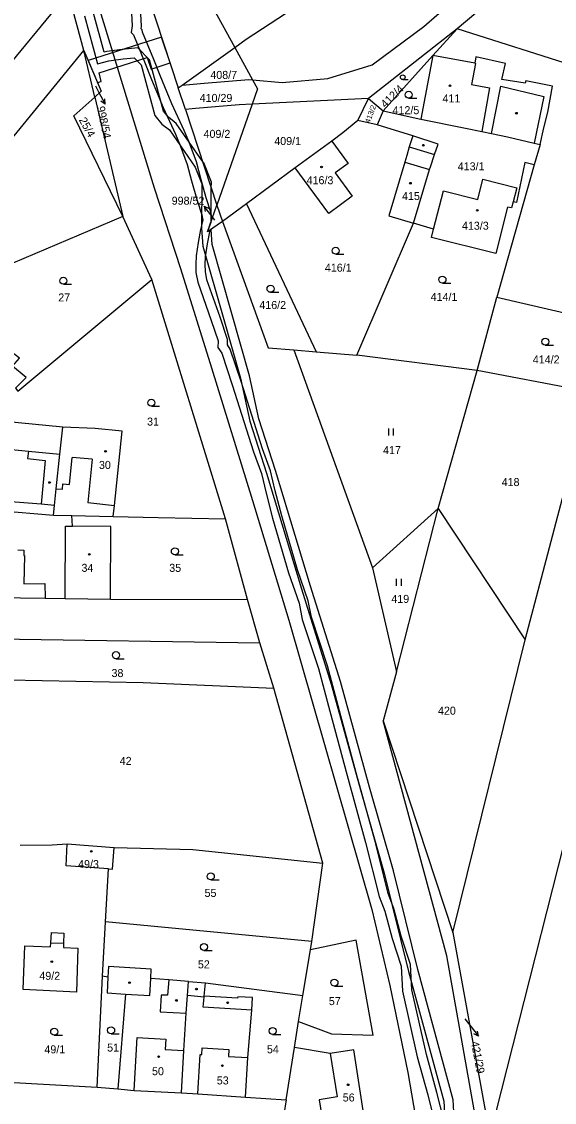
# Model space of a CAD drawing. Extents: x -757266 to -753360, y -1162585 to -1157740.
# Drawn here: x -754656.1 to -754542.9, y -1161271.1 to -1161041.7 of the extents above; entities that cross this region are included whole.
import ezdxf

# ---------------------------------------------------------------- set-up
doc = ezdxf.new("R2010")
doc.units = 0
for name, color, linetype in [('Hranice parcel', 7, 'Continuous'), ('Parcelní čísla', 7, 'Continuous'), ('Pop  PČ popisy', 7, 'Continuous'), ('Poz předměty', 7, 'Continuous'), ('Vnitřní kresba', 7, 'Continuous'), ('Věcná břemena k části', 7, 'Continuous'), ('Značky budov', 7, 'Continuous'), ('Značky kultur', 7, 'Continuous')]:
    doc.layers.add(name, color=color, linetype=linetype)

msp = doc.modelspace()

# ---------------------------------------------------------------- linework, layer by layer
at = {"layer": 'Hranice parcel'}
for p, q in [((-754505.44, -1160994.03), (-754563.51, -1161043.2)), ((-754632.76, -1161025.61), (-754622.81, -1161055.74)), ((-754646.22, -1161035.54), (-754676.57, -1161072.39)), ((-754642.86, -1161047.81), (-754646.22, -1161035.54)), ((-754616.16, -1161037.43), (-754610.8, -1161047.18)), ((-754563.51, -1161043.2), (-754582.39, -1161057.99)), ((-754563.51, -1161043.2), (-754568.69, -1161048.85)), ((-754518.76, -1161057.4), (-754563.51, -1161043.2)), ((-754640.55, -1161057.68), (-754642.86, -1161047.81)), ((-754622, -1161055.16), (-754610.8, -1161047.18)), ((-754610.8, -1161047.18), (-754607.04, -1161054.04)), ((-754579.29, -1161060.63), (-754568.69, -1161048.85)), ((-754568.69, -1161048.85), (-754571.3, -1161062.39)), ((-754622.81, -1161055.74), (-754622, -1161055.16)), ((-754621.3, -1161060.33), (-754622.81, -1161055.74)), ((-754640.55, -1161057.68), (-754634.62, -1161083.05)), ((-754582.39, -1161057.99), (-754607.11, -1161059.19)), ((-754584.62, -1161062.68), (-754582.39, -1161057.99)), ((-754582.39, -1161057.99), (-754579.29, -1161060.63)), ((-754621.3, -1161060.33), (-754614.59, -1161080.64)), ((-754607.11, -1161059.19), (-754614.59, -1161080.64)), ((-754580.56, -1161063.61), (-754584.62, -1161062.68)), ((-754579.29, -1161060.63), (-754580.56, -1161063.61)), ((-754579.29, -1161060.63), (-754571.3, -1161062.39)), ((-754572.98, -1161065.95), (-754580.56, -1161063.61)), ((-754590.21, -1161067.05), (-754597.94, -1161072.74)), ((-754545.93, -1161067.76), (-754547.16, -1161072.1)), ((-754597.94, -1161072.74), (-754608.34, -1161080.38)), ((-754547.16, -1161072.1), (-754555.14, -1161100.2)), ((-754614.59, -1161080.64), (-754613.44, -1161084.13)), ((-754608.34, -1161080.38), (-754613.44, -1161084.13)), ((-754608.34, -1161080.38), (-754593.54, -1161111.8)), ((-754628.41, -1161096.45), (-754634.62, -1161083.05)), ((-754584.85, -1161112.49), (-754572.82, -1161084.47)), ((-754568.54, -1161085.77), (-754572.82, -1161084.47)), ((-754612.8, -1161147.21), (-754628.41, -1161096.45)), ((-754559.29, -1161115.76), (-754555.14, -1161100.2)), ((-754555.14, -1161100.2), (-754531.49, -1161105.67)), ((-754598.26, -1161111.37), (-754593.54, -1161111.8)), ((-754598.26, -1161111.37), (-754581.57, -1161157.63)), ((-754593.54, -1161111.8), (-754584.85, -1161112.49)), ((-754559.29, -1161115.76), (-754584.85, -1161112.49)), ((-754567.57, -1161145.06), (-754559.29, -1161115.76)), ((-754535.27, -1161120.34), (-754559.29, -1161115.76)), ((-754549.12, -1161172.93), (-754535.27, -1161120.34)), ((-754649.33, -1161146.5), (-754649.15, -1161144.41)), ((-754581.57, -1161157.63), (-754567.57, -1161145.06)), ((-754576.47, -1161179.76), (-754567.57, -1161145.06)), ((-754567.57, -1161145.06), (-754549.12, -1161172.93)), ((-754661.09, -1161145.5), (-754649.33, -1161146.5)), ((-754649.33, -1161146.5), (-754645.44, -1161146.57)), ((-754645.44, -1161146.57), (-754636.62, -1161146.74)), ((-754608.08, -1161164.36), (-754612.8, -1161147.21)), ((-754581.57, -1161157.63), (-754576.47, -1161179.76)), ((-754637.21, -1161164.28), (-754608.08, -1161164.36)), ((-754605.47, -1161173.57), (-754608.08, -1161164.36)), ((-754665.83, -1161172.68), (-754605.47, -1161173.57)), ((-754564.47, -1161235.05), (-754549.12, -1161172.93)), ((-754602.53, -1161183.22), (-754605.47, -1161173.57)), ((-754576.47, -1161179.76), (-754579.29, -1161190.13)), ((-754592.11, -1161220.36), (-754602.53, -1161183.22)), ((-754579.29, -1161190.13), (-754564.47, -1161235.05)), ((-754646.41, -1161216.24), (-754636.47, -1161217.01)), ((-754594.41, -1161237.01), (-754592.11, -1161220.36)), ((-754638.25, -1161232.81), (-754637.67, -1161221.55)), ((-754638.93, -1161244.35), (-754638.25, -1161232.81)), ((-754594.41, -1161237.01), (-754638.25, -1161232.81)), ((-754594.71, -1161238.77), (-754594.41, -1161237.01)), ((-754564.47, -1161235.05), (-754556.62, -1161278.19)), ((-754596.35, -1161248.45), (-754594.71, -1161238.77)), ((-754640.08, -1161267.9), (-754638.93, -1161244.35)), ((-754637.77, -1161244.58), (-754638.93, -1161244.35)), ((-754620.66, -1161245.49), (-754617.05, -1161245.76)), ((-754617.05, -1161245.76), (-754596.35, -1161248.45)), ((-754597.23, -1161253.96), (-754596.35, -1161248.45)), ((-754598.11, -1161259.48), (-754597.23, -1161253.96)), ((-754599.88, -1161270.57), (-754598.11, -1161259.48)), ((-754659, -1161266.85), (-754640.08, -1161267.9)), ((-754640.08, -1161267.9), (-754635.66, -1161268.3)), ((-754608.55, -1161270.04), (-754599.88, -1161270.57)), ((-754599.88, -1161270.57), (-754600.35, -1161273.7))]:
    msp.add_line(p, q, dxfattribs=at)
for points in [[(-754607.04, -1161054.04), (-754600.71, -1161054.59), (-754591, -1161053.78), (-754581.59, -1161050.82), (-754570.6, -1161042.7), (-754567.85, -1161040.32), (-754537.32, -1161014.22), (-754507.32, -1160989.09), (-754497.32, -1160980.69)], [(-754484.16, -1160981.35), (-754485.81, -1160996.01), (-754494.05, -1161034.11), (-754504.67, -1161074), (-754524.03, -1161152.27), (-754534.83, -1161192.53), (-754556.62, -1161278.19)], [(-754610.8, -1161047.18), (-754608.35, -1161045.43), (-754574.49, -1161023.27), (-754573.45, -1161022.29)], [(-754669.45, -1161077.24), (-754667.83, -1161078.26), (-754642.86, -1161047.81)], [(-754642.86, -1161047.81), (-754639.19, -1161056.46), (-754640.55, -1161057.68)], [(-754545.93, -1161067.76), (-754545.16, -1161064.25), (-754544.31, -1161060.88), (-754543.26, -1161055.36), (-754548.96, -1161054.22), (-754549.06, -1161054.72), (-754554.02, -1161053.97), (-754553.26, -1161050.6), (-754559.61, -1161049.14), (-754559.81, -1161050.52), (-754568.69, -1161048.85)], [(-754622, -1161055.16), (-754617.31, -1161054.77), (-754607.79, -1161053.97), (-754607.04, -1161054.04)], [(-754607.04, -1161054.04), (-754605.98, -1161055.96), (-754607.11, -1161059.19)], [(-754634.62, -1161083.05), (-754645, -1161061.66), (-754640.55, -1161057.68)], [(-754607.11, -1161059.19), (-754609.86, -1161059.32), (-754619.16, -1161060.14), (-754621.3, -1161060.33)], [(-754584.62, -1161062.68), (-754587.82, -1161065.29), (-754590.21, -1161067.05)], [(-754571.3, -1161062.39), (-754561.77, -1161064.32), (-754558.31, -1161065.03), (-754556.27, -1161065.44), (-754552.88, -1161066.13), (-754547.19, -1161067.47), (-754545.93, -1161067.76)], [(-754590.21, -1161067.05), (-754586.71, -1161071.81), (-754589.44, -1161073.81), (-754585.83, -1161078.71), (-754590.84, -1161082.39), (-754597.94, -1161072.74)], [(-754572.98, -1161065.95), (-754573.74, -1161068.29), (-754574.26, -1161070.08), (-754574.69, -1161071.51), (-754578.09, -1161082.9), (-754572.82, -1161084.47)], [(-754572.82, -1161084.47), (-754569.41, -1161073.09), (-754569.24, -1161072.51), (-754568.34, -1161069.88), (-754567.59, -1161067.7), (-754572.98, -1161065.95)], [(-754547.16, -1161072.1), (-754549.18, -1161071.59), (-754550.95, -1161080.09), (-754551.66, -1161079.95)], [(-754568.54, -1161085.77), (-754566.47, -1161077.63), (-754559.16, -1161079.45), (-754558.08, -1161075.11), (-754550.85, -1161076.97), (-754551.66, -1161079.95)], [(-754613.44, -1161084.13), (-754616.58, -1161086.33), (-754614.59, -1161080.64)], [(-754551.66, -1161079.95), (-754552, -1161081.21), (-754552.83, -1161081.07), (-754555.33, -1161090.92), (-754568.98, -1161087.48), (-754568.54, -1161085.77)], [(-754634.62, -1161083.05), (-754665.07, -1161095.95), (-754672.4, -1161100.99)], [(-754613.44, -1161084.13), (-754603.74, -1161110.96), (-754598.26, -1161111.37)], [(-754657.43, -1161119.52), (-754656.9, -1161120.17), (-754628.41, -1161096.45)], [(-754657.43, -1161119.52), (-754655.13, -1161117.27), (-754658.05, -1161114.8), (-754656.58, -1161113.13), (-754672.4, -1161100.99)], [(-754647.38, -1161127.78), (-754662.67, -1161126.26), (-754663.15, -1161125.55)], [(-754649.15, -1161144.41), (-754648.77, -1161140.87), (-754647.99, -1161133.49), (-754647.38, -1161127.78)], [(-754636.62, -1161146.74), (-754636.38, -1161144.39), (-754634.76, -1161128.64), (-754640.44, -1161128.06), (-754647.38, -1161127.78)], [(-754649.15, -1161144.41), (-754651.96, -1161144.14), (-754667.65, -1161142.92), (-754668.31, -1161144.31)], [(-754637.21, -1161164.28), (-754637.18, -1161148.88), (-754645.26, -1161148.81), (-754645.44, -1161146.57)], [(-754636.62, -1161146.74), (-754627.07, -1161146.93), (-754612.8, -1161147.21)], [(-754662.23, -1161163.96), (-754661.63, -1161163.97), (-754651.09, -1161164.1), (-754646.82, -1161164.15), (-754637.21, -1161164.28)], [(-754666.09, -1161181.29), (-754630.3, -1161182.02), (-754602.53, -1161183.22)], [(-754559.89, -1161425.06), (-754553.59, -1161342.24), (-754557.22, -1161287.88), (-754565.71, -1161240.05), (-754579.29, -1161190.13)], [(-754656.42, -1161216.52), (-754649.58, -1161216.43), (-754646.41, -1161216.24)], [(-754637.67, -1161221.55), (-754646.62, -1161220.9), (-754646.41, -1161216.24)], [(-754637.67, -1161221.55), (-754636.82, -1161221.61), (-754636.47, -1161217.01)], [(-754636.47, -1161217.01), (-754619.72, -1161217.48), (-754592.11, -1161220.36)], [(-754644.14, -1161238.37), (-754644.44, -1161247.72), (-754655.8, -1161247.17), (-754655.4, -1161237.87), (-754649.97, -1161238.11), (-754649.93, -1161237.24), (-754649.77, -1161235.07), (-754647.1, -1161235.19), (-754647.2, -1161237.34), (-754647.23, -1161238.24), (-754644.14, -1161238.37)], [(-754597.23, -1161253.96), (-754590.22, -1161256.57), (-754581.4, -1161256.88), (-754584.99, -1161236.67), (-754594.71, -1161238.77)], [(-754620.66, -1161245.49), (-754624.83, -1161245.15), (-754628.68, -1161244.83), (-754628.59, -1161242.88), (-754637.64, -1161242.32), (-754637.77, -1161244.58)], [(-754637.77, -1161244.58), (-754637.96, -1161247.91), (-754634.04, -1161248.13), (-754635.66, -1161268.3)], [(-754622.14, -1161269.12), (-754621.61, -1161260.15), (-754621.14, -1161252.21), (-754620.88, -1161248.47), (-754620.66, -1161245.49)], [(-754608.55, -1161270.04), (-754608.02, -1161261.64), (-754607.18, -1161251.53), (-754607.05, -1161248.9), (-754610.18, -1161248.71), (-754610.2, -1161249.03), (-754617.31, -1161248.59), (-754617.05, -1161245.76)], [(-754600.35, -1161273.7), (-754591.79, -1161277.13), (-754583.11, -1161275.65), (-754585.54, -1161259.98), (-754590.52, -1161260.79), (-754598.11, -1161259.48)], [(-754635.66, -1161268.3), (-754632.18, -1161268.61), (-754622.14, -1161269.12)], [(-754622.14, -1161269.12), (-754618.65, -1161269.35), (-754608.55, -1161270.04)]]:
    msp.add_lwpolyline(points, dxfattribs=at)
at = {"layer": 'Pop  PČ popisy'}
for p, q in [((-754640.43, -1161055.34), (-754639.77, -1161056.56)), ((-754639.77, -1161056.56), (-754638.361, -1161059.21)), ((-754638.361, -1161059.21), (-754638.389, -1161058.09)), ((-754638.361, -1161059.21), (-754639.273, -1161058.561)), ((-754615.48, -1161083.26), (-754617.286, -1161080.863)), ((-754617.286, -1161080.863), (-754616.283, -1161081.362)), ((-754617.286, -1161080.863), (-754617.083, -1161081.964)), ((-754615.03, -1161083.85), (-754615.48, -1161083.26)), ((-754561.91, -1161253.39), (-754560.87, -1161254.72)), ((-754560.87, -1161254.72), (-754559.022, -1161257.085)), ((-754559.022, -1161257.085), (-754560.034, -1161256.604)), ((-754559.022, -1161257.085), (-754559.244, -1161255.987))]:
    msp.add_line(p, q, dxfattribs=at)
at = {"layer": 'Poz předměty'}
for p, q in [((-754640.36, -1161036.44), (-754627.93, -1161076.96)), ((-754627.93, -1161076.96), (-754622.34, -1161094.06)), ((-754622.34, -1161094.06), (-754615.74, -1161115.17)), ((-754615.74, -1161115.17), (-754607.03, -1161143.36)), ((-754607.03, -1161143.36), (-754599.3, -1161168.73)), ((-754599.3, -1161168.73), (-754581.68, -1161230.2)), ((-754581.68, -1161230.2), (-754577.88, -1161246.36)), ((-754577.88, -1161246.36), (-754574.02, -1161264.81)), ((-754574.02, -1161264.81), (-754570.84, -1161283.4))]:
    msp.add_line(p, q, dxfattribs=at)
at = {"layer": 'Vnitřní kresba'}
for p, q in [((-754559.64, -1161050.55), (-754560.51, -1161055)), ((-754559.81, -1161050.52), (-754559.64, -1161050.55)), ((-754560.51, -1161055), (-754556.64, -1161055.76)), ((-754556.64, -1161055.76), (-754558.31, -1161065.03)), ((-754556.27, -1161065.44), (-754554.27, -1161055.4)), ((-754554.27, -1161055.4), (-754545.16, -1161057.57)), ((-754545.16, -1161057.57), (-754547.19, -1161067.47)), ((-754573.74, -1161068.29), (-754568.34, -1161069.88)), ((-754574.69, -1161071.51), (-754569.41, -1161073.09)), ((-754660.39, -1161132.29), (-754654.63, -1161132.85)), ((-754654.63, -1161132.85), (-754654.86, -1161134.46)), ((-754654.63, -1161132.85), (-754647.99, -1161133.49)), ((-754654.86, -1161134.46), (-754651.11, -1161134.87)), ((-754651.11, -1161134.87), (-754651.96, -1161144.14)), ((-754645.92, -1161139.96), (-754645.34, -1161134.21)), ((-754641.11, -1161134.57), (-754645.34, -1161134.21)), ((-754641.11, -1161134.57), (-754642.04, -1161143.75)), ((-754647.42, -1161140.96), (-754647.32, -1161139.81)), ((-754647.32, -1161139.81), (-754645.92, -1161139.96)), ((-754648.77, -1161140.87), (-754647.42, -1161140.96)), ((-754642.04, -1161143.75), (-754636.38, -1161144.39)), ((-754646.82, -1161164.15), (-754646.81, -1161148.79)), ((-754646.81, -1161148.79), (-754645.26, -1161148.81)), ((-754656.94, -1161153.84), (-754655.64, -1161153.92)), ((-754655.64, -1161153.92), (-754655.65, -1161155.04)), ((-754655.65, -1161155.04), (-754655.48, -1161155.04)), ((-754655.48, -1161155.04), (-754655.63, -1161161.02)), ((-754655.63, -1161161.02), (-754651.15, -1161160.94)), ((-754651.15, -1161160.94), (-754651.09, -1161164.1)), ((-754649.93, -1161237.24), (-754647.2, -1161237.34)), ((-754628.85, -1161248.43), (-754628.68, -1161244.83)), ((-754624.83, -1161245.15), (-754625.09, -1161248.38)), ((-754634.04, -1161248.13), (-754628.85, -1161248.43)), ((-754626.44, -1161248.41), (-754626.66, -1161251.93)), ((-754625.09, -1161248.38), (-754626.44, -1161248.41)), ((-754617.33, -1161248.78), (-754620.88, -1161248.47)), ((-754617.33, -1161248.78), (-754617.31, -1161248.59)), ((-754617.53, -1161250.93), (-754617.33, -1161248.78)), ((-754607.18, -1161251.53), (-754617.53, -1161250.93)), ((-754626.66, -1161251.93), (-754621.14, -1161252.21)), ((-754632.18, -1161268.61), (-754631.55, -1161257.36)), ((-754631.55, -1161257.36), (-754625.47, -1161257.75)), ((-754625.47, -1161257.75), (-754625.63, -1161259.91)), ((-754625.63, -1161259.91), (-754621.61, -1161260.15)), ((-754617.84, -1161261.01), (-754617.73, -1161259.53)), ((-754617.73, -1161259.53), (-754612.07, -1161259.92)), ((-754612.07, -1161259.92), (-754612.14, -1161261.38)), ((-754618.65, -1161269.35), (-754618.14, -1161261)), ((-754618.14, -1161261), (-754617.84, -1161261.01)), ((-754612.14, -1161261.38), (-754608.02, -1161261.64)), ((-754590.52, -1161260.79), (-754589.08, -1161269.98)), ((-754589.08, -1161269.98), (-754592.86, -1161270.58)), ((-754592.86, -1161270.58), (-754591.79, -1161277.13))]:
    msp.add_line(p, q, dxfattribs=at)
at = {"layer": 'Věcná břemena k části'}
for points in [[(-754642.72, -1161040.43), (-754640.01, -1161050.67), (-754637.58, -1161049.98), (-754634.55, -1161049.56), (-754632.17, -1161049.34), (-754630.73, -1161050.84), (-754627.76, -1161061.63), (-754626.3, -1161063.43), (-754624.71, -1161064.68), (-754619.19, -1161072.59), (-754617.78, -1161076.15), (-754617.85, -1161085.53), (-754617.58, -1161089.33), (-754613.3, -1161104.42), (-754609.61, -1161117.4), (-754607.64, -1161126.52), (-754604.04, -1161137.57), (-754596.65, -1161162.11), (-754590.29, -1161182.35), (-754584.12, -1161204.81), (-754579.03, -1161222.51), (-754573.87, -1161243.37), (-754566.41, -1161270.91), (-754565.96, -1161278.43)], [(-754563.96, -1161278.25), (-754564.43, -1161270.59), (-754571.93, -1161242.91), (-754577.09, -1161222.01), (-754582.2, -1161204.25), (-754588.37, -1161181.77), (-754594.73, -1161161.57), (-754602.12, -1161137.01), (-754605.7, -1161125.99), (-754607.67, -1161116.9), (-754611.5, -1161103.46), (-754615.6, -1161088.97), (-754615.83, -1161085.8), (-754616.58, -1161086.33), (-754615.84, -1161084.22), (-754615.79, -1161077.01), (-754615.78, -1161075.77), (-754617.41, -1161071.63), (-754617.71, -1161071.2), (-754623.23, -1161063.3), (-754624.88, -1161061.99), (-754625.94, -1161060.69), (-754628.93, -1161049.82), (-754631.39, -1161047.26), (-754634.77, -1161047.58), (-754638, -1161048.02), (-754638.59, -1161048.19), (-754640.8, -1161039.89)], [(-754632.74, -1161039.91), (-754632.63, -1161042.58), (-754632.82, -1161043.96), (-754632.34, -1161044.47), (-754629.99, -1161050.22), (-754628.47, -1161053.98), (-754626.01, -1161059.9), (-754623.39, -1161065.59), (-754622.39, -1161067.97), (-754620.89, -1161072), (-754620, -1161075.45), (-754618.83, -1161079.68), (-754617.82, -1161082.68), (-754617.56, -1161083.84), (-754618.09, -1161085.82), (-754618.57, -1161088.58), (-754619, -1161091.39), (-754619.1, -1161093.25), (-754619.05, -1161094.97), (-754618.64, -1161097.01), (-754615.79, -1161105.14), (-754614.34, -1161109.45), (-754614.38, -1161110.88), (-754613.58, -1161112.08), (-754611.36, -1161118.76), (-754606.83, -1161133.04), (-754605.13, -1161137.65), (-754604.15, -1161141.81), (-754602.77, -1161147.13), (-754599.4, -1161158.69), (-754597.12, -1161165.16), (-754596.45, -1161168.65), (-754593.03, -1161179.04), (-754590.59, -1161188.06), (-754586.92, -1161201.71), (-754583, -1161215.93), (-754580.11, -1161227.41), (-754578.92, -1161230.55), (-754577.37, -1161236.38), (-754575.43, -1161242.23), (-754575.19, -1161247.55), (-754572.02, -1161261.49), (-754569.81, -1161269.52), (-754568.3, -1161275.53)], [(-754624.18, -1161059.11), (-754626.67, -1161053.08), (-754628.04, -1161049.71), (-754630.42, -1161043.88), (-754630.51, -1161043.44), (-754630.7, -1161043.24), (-754630.63, -1161042.67), (-754630.74, -1161040.05)], [(-754566.34, -1161275.16), (-754567.88, -1161269.01), (-754570.09, -1161260.99), (-754573.2, -1161247.28), (-754573.45, -1161241.87), (-754575.45, -1161235.82), (-754577.01, -1161229.95), (-754578.19, -1161226.82), (-754581.06, -1161215.46), (-754584.99, -1161201.2), (-754588.53, -1161188.01), (-754591.12, -1161178.46), (-754594.51, -1161168.14), (-754595.18, -1161164.63), (-754597.5, -1161158.06), (-754600.84, -1161146.61), (-754602.21, -1161141.32), (-754603.21, -1161137.08), (-754604.94, -1161132.39), (-754609.47, -1161118.12), (-754611.76, -1161111.19), (-754612.36, -1161110.29), (-754612.34, -1161109.15), (-754613.92, -1161104.41), (-754616.71, -1161096.47), (-754617.05, -1161094.75), (-754617.1, -1161093.25), (-754617, -1161091.61), (-754616.59, -1161088.87), (-754616.06, -1161085.96), (-754616.58, -1161086.33), (-754615.59, -1161083.49), (-754615.89, -1161082.14), (-754616.92, -1161079.06), (-754618.05, -1161075.01), (-754618.97, -1161071.41), (-754620.52, -1161067.25), (-754621.57, -1161064.77), (-754624.18, -1161059.11)]]:
    msp.add_lwpolyline(points, dxfattribs=at)
msp.add_lwpolyline([(-754639.17, -1161054.38), (-754639.6, -1161052.53), (-754629.42, -1161049.29), (-754628.6, -1161051.76), (-754624.57, -1161050.42), (-754626.35, -1161045.01), (-754641.97, -1161049.9), (-754639.99, -1161054.57)], close=True, dxfattribs=at)
at = {"layer": 'Značky budov'}
for centre in [(-754565.0568, -1161055.2992), (-754550.9468, -1161061.1192), (-754570.7368, -1161067.9092), (-754592.3668, -1161072.5292), (-754573.4668, -1161075.9792), (-754559.2768, -1161081.7392), (-754638.2768, -1161132.9192), (-754650.1668, -1161139.5292), (-754641.7268, -1161154.7892), (-754641.2968, -1161217.8392), (-754649.6868, -1161241.2792), (-754633.1668, -1161245.7192), (-754618.9568, -1161247.0892), (-754623.2068, -1161249.4992), (-754612.3068, -1161249.9992), (-754626.9868, -1161261.4492), (-754613.4368, -1161263.3492), (-754586.7168, -1161267.3992)]:
    msp.add_circle(centre, 0.175, dxfattribs=at)
at = {"layer": 'Značky kultur'}
for p, q in [((-754575.115, -1161053.99), (-754573.943, -1161053.99)), ((-754573.853, -1161057.95), (-754572.103, -1161057.95)), ((-754589.353, -1161091.07), (-754587.603, -1161091.07)), ((-754566.673, -1161097.2), (-754564.923, -1161097.2)), ((-754647.233, -1161097.44), (-754645.483, -1161097.44)), ((-754603.203, -1161099.15), (-754601.453, -1161099.15)), ((-754544.823, -1161110.38), (-754543.073, -1161110.38)), ((-754628.533, -1161123.34), (-754626.783, -1161123.34)), ((-754578.051, -1161129.56), (-754578.051, -1161128.06)), ((-754577.05, -1161129.56), (-754577.05, -1161128.06)), ((-754623.533, -1161154.89), (-754621.783, -1161154.89)), ((-754576.411, -1161161.46), (-754576.411, -1161159.96)), ((-754575.41, -1161161.46), (-754575.41, -1161159.96)), ((-754636.053, -1161176.94), (-754634.303, -1161176.94)), ((-754615.903, -1161223.91), (-754614.153, -1161223.91)), ((-754617.353, -1161238.9), (-754615.603, -1161238.9)), ((-754589.623, -1161246.46), (-754587.873, -1161246.46)), ((-754649.173, -1161256.89), (-754647.423, -1161256.89)), ((-754637.093, -1161256.59), (-754635.343, -1161256.59)), ((-754602.763, -1161256.73), (-754601.013, -1161256.73))]:
    msp.add_line(p, q, dxfattribs=at)
for centre, radius in [((-754575.1152, -1161053.4874), 0.5025), ((-754573.8529, -1161057.1998), 0.75), ((-754589.3529, -1161090.3198), 0.75), ((-754647.2329, -1161096.6898), 0.75), ((-754566.6729, -1161096.4498), 0.75), ((-754603.2029, -1161098.3998), 0.75), ((-754544.8229, -1161109.6298), 0.75), ((-754628.5329, -1161122.5898), 0.75), ((-754623.5329, -1161154.1398), 0.75), ((-754636.0529, -1161176.1898), 0.75), ((-754615.9029, -1161223.1598), 0.75), ((-754617.3529, -1161238.1498), 0.75), ((-754589.6229, -1161245.7098), 0.75), ((-754649.1729, -1161256.1398), 0.75), ((-754637.0929, -1161255.8398), 0.75), ((-754602.7629, -1161255.9798), 0.75)]:
    msp.add_circle(centre, radius, dxfattribs=at)

# ---------------------------------------------------------------- texts
at = {"layer": 'Parcelní čísla'}
for s, p in [('408/7', (-754616, -1161053.84)), ('410/29', (-754618.27, -1161058.73)), ('411', (-754566.66, -1161058.83)), ('412/5', (-754577.28, -1161061.33)), ('409/2', (-754617.44, -1161066.36)), ('409/1', (-754602.41, -1161067.88)), ('413/1', (-754563.428, -1161073.25)), ('416/3', (-754595.54, -1161076.2)), ('998/52', (-754624.215, -1161080.55)), ('415', (-754575.26, -1161079.55)), ('413/3', (-754562.53, -1161085.86)), ('416/1', (-754591.66, -1161094.77)), ('27', (-754648.32, -1161101.09)), ('414/1', (-754569.19, -1161100.98)), ('416/2', (-754605.59, -1161102.69)), ('414/2', (-754547.47, -1161114.26)), ('31', (-754629.44, -1161127.44)), ('417', (-754579.29, -1161133.49)), ('30', (-754639.67, -1161136.65)), ('418', (-754554.09, -1161140.29)), ('34', (-754643.38, -1161158.5)), ('35', (-754624.73, -1161158.5)), ('419', (-754577.54, -1161165.09)), ('38', (-754637, -1161180.84)), ('420', (-754567.62, -1161188.83)), ('42', (-754635.26, -1161199.49)), ('49/3', (-754644.1, -1161221.39)), ('55', (-754617.23, -1161227.52)), ('52', (-754618.65, -1161242.69)), ('49/2', (-754652.34, -1161245.12)), ('57', (-754590.82, -1161250.49)), ('49/1', (-754651.26, -1161260.73)), ('51', (-754637.93, -1161260.35)), ('54', (-754603.97, -1161260.71)), ('50', (-754628.39, -1161265.37)), ('53', (-754614.63, -1161267.33)), ('56', (-754587.86, -1161270.95))]:
    msp.add_text(s, height=1.7, dxfattribs=at).set_placement(p)
for s, height, rotation, p in [('412/4', 1.7, 43.999997, (-754578.829, -1161060.101)), ('998/54', 1.7, 282, (-754640.138, -1161059.829)), ('413/2', 1.139, 68.999997, (-754582.15, -1161063.337)), ('25/4', 1.7, 298.999997, (-754643.983, -1161062.562)), ('421/29', 1.7, 281, (-754560.636, -1161258.323))]:
    msp.add_text(s, height=height, rotation=rotation, dxfattribs=at).set_placement(p)

doc.saveas('drawing.dxf')
